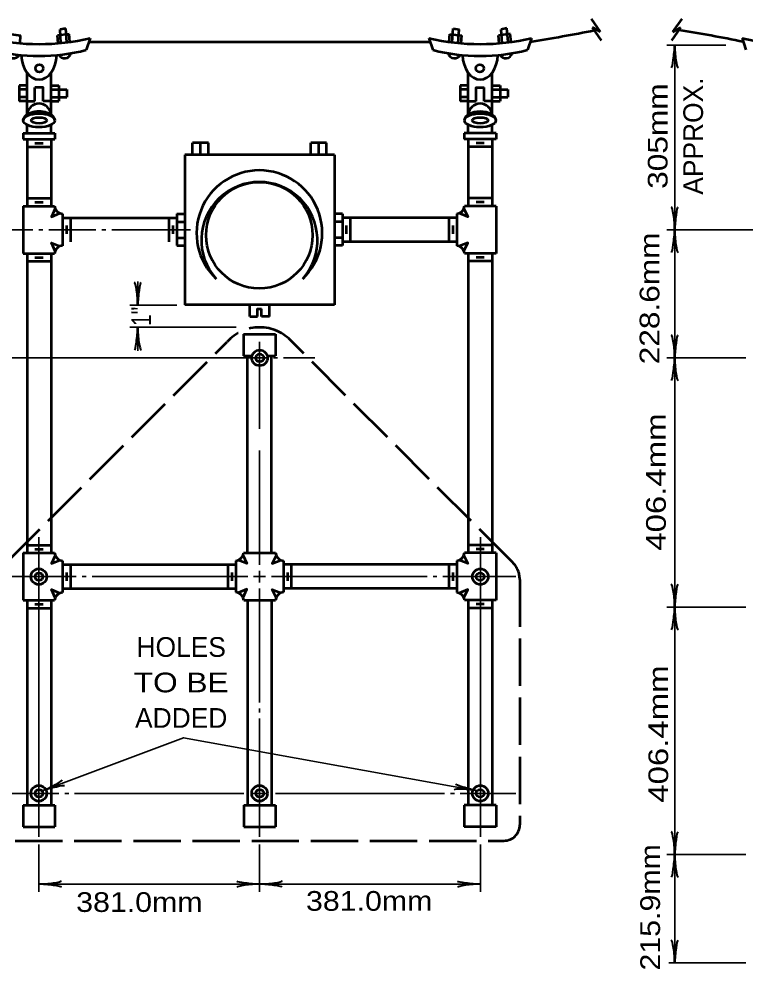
# Model space of a CAD drawing. Extents: x -35 to 821, y -10 to 534.
# Drawn here: x 78 to 188.7, y 242.7 to 387.3 of the extents above; entities that cross this region are included whole.
import ezdxf
from ezdxf.enums import TextEntityAlignment as Align

# ---------------------------------------------------------------- set-up
doc = ezdxf.new("R2010")
doc.units = 0
doc.header["$LTSCALE"] = 1.2
doc.linetypes.add('LONG_DASHED', pattern=[7.5, 6, -1.5])
doc.layers.add('1', color=7, linetype='Continuous', lineweight=35)

msp = doc.modelspace()

# ---------------------------------------------------------------- linework, layer by layer
at = {"layer": '1', "lineweight": 53}
for p, q in [((166.54, 385.374), (165.163, 387.34)), ((177.582, 385.374), (178.959, 387.34)), ((76.491, 385.075), (78.275, 384.834)), ((78.192, 383.649), (78.275, 384.834)), ((85.696, 385.031), (83.895, 384.831)), ((83.977, 383.649), (83.895, 384.831)), ((85.184, 385.898), (84.281, 385.76)), ((84.427, 383.665), (84.281, 385.76)), ((85.33, 383.803), (85.184, 385.898)), ((85.778, 383.85), (85.696, 385.031)), ((143.534, 383.85), (143.616, 385.031)), ((143.616, 385.031), (145.417, 384.831)), ((143.982, 383.803), (144.128, 385.898)), ((144.128, 385.898), (145.031, 385.76)), ((144.885, 383.665), (145.031, 385.76)), ((145.335, 383.649), (145.417, 384.831)), ((152.821, 385.075), (151.037, 384.834)), ((151.12, 383.649), (151.037, 384.834)), ((152.294, 385.932), (151.424, 385.763)), ((151.57, 383.668), (151.424, 385.763)), ((152.477, 383.84), (152.294, 385.932)), ((152.928, 383.851), (152.821, 385.075)), ((166.723, 384.055), (165.346, 386.021)), ((166.54, 385.374), (165.346, 386.021)), ((177.399, 384.055), (178.776, 386.021)), ((177.582, 385.374), (178.776, 386.021)), ((88.883, 384.427), (88.283, 382.627)), ((88.693, 383.857), (140.619, 383.857)), ((140.429, 384.427), (141.029, 382.627)), ((156.029, 384.427), (155.429, 382.627)), ((188.093, 384.427), (188.693, 382.627)), ((79.256, 372.783), (79.256, 379.155)), ((82.91, 372.783), (82.91, 379.155)), ((146.402, 372.783), (146.402, 379.155)), ((150.056, 372.783), (150.056, 379.155)), ((79.256, 377.227), (78.056, 377.227)), ((78.056, 377.227), (78.056, 374.827)), ((79.256, 376.627), (78.056, 376.627)), ((80.456, 374.827), (80.456, 376.927)), ((82.91, 377.227), (84.11, 377.227)), ((82.91, 376.627), (85.31, 376.627)), ((84.11, 377.227), (84.11, 374.827)), ((85.31, 376.627), (85.31, 375.427)), ((146.402, 377.227), (145.202, 377.227)), ((145.202, 377.227), (145.202, 374.827)), ((146.402, 376.627), (145.202, 376.627)), ((148.856, 374.827), (148.856, 376.927)), ((150.056, 377.227), (151.256, 377.227)), ((150.056, 376.627), (152.456, 376.627)), ((151.256, 377.227), (151.256, 374.827)), ((152.456, 376.627), (152.456, 375.427)), ((79.256, 375.427), (78.056, 375.427)), ((79.256, 374.827), (78.056, 374.827)), ((79.256, 374.827), (80.456, 374.827)), ((82.91, 374.827), (81.71, 374.827)), ((82.91, 375.427), (85.31, 375.427)), ((82.91, 374.827), (84.11, 374.827)), ((146.402, 375.427), (145.202, 375.427)), ((146.402, 374.827), (145.202, 374.827)), ((146.402, 374.827), (147.602, 374.827)), ((150.056, 374.827), (148.856, 374.827)), ((150.056, 375.427), (152.456, 375.427)), ((150.056, 374.827), (151.256, 374.827)), ((79.256, 369.958), (79.256, 371.227)), ((82.91, 369.958), (82.91, 371.227)), ((146.402, 369.958), (146.402, 371.227)), ((150.056, 369.958), (150.056, 371.227)), ((78.656, 369.958), (83.51, 369.958)), ((78.656, 369.958), (78.656, 369.058)), ((78.656, 369.058), (83.51, 369.058)), ((79.256, 369.058), (79.256, 358.858)), ((82.91, 369.058), (82.91, 358.858)), ((83.51, 369.958), (83.51, 369.058)), ((150.656, 369.958), (145.802, 369.958)), ((145.802, 369.958), (145.802, 369.058)), ((150.656, 369.058), (145.802, 369.058)), ((146.402, 369.058), (146.402, 358.858)), ((150.056, 369.058), (150.056, 358.858)), ((150.656, 369.958), (150.656, 369.058)), ((79.256, 367.858), (82.91, 367.858)), ((80.456, 368.458), (81.71, 368.458)), ((104.456, 366.685), (104.456, 368.485)), ((106.856, 368.485), (104.456, 368.485)), ((105.656, 366.685), (105.656, 368.485)), ((106.856, 366.685), (106.856, 368.485)), ((122.456, 366.685), (122.456, 368.485)), ((124.856, 368.485), (122.456, 368.485)), ((123.656, 366.685), (123.656, 368.485)), ((124.856, 366.685), (124.856, 368.485)), ((150.056, 367.858), (146.402, 367.858)), ((148.856, 368.458), (147.602, 368.458)), ((126.056, 366.685), (103.256, 366.685)), ((103.256, 366.685), (103.256, 343.843)), ((126.056, 366.685), (126.056, 343.843)), ((78.656, 358.858), (83.455, 358.858)), ((78.656, 358.858), (78.656, 351.658)), ((79.256, 360.058), (82.91, 360.058)), ((80.456, 359.458), (81.71, 359.458)), ((150.656, 358.858), (145.857, 358.858)), ((150.056, 360.058), (146.402, 360.058)), ((148.856, 359.458), (147.602, 359.458)), ((150.656, 358.858), (150.656, 351.658)), ((84.656, 357.685), (84.656, 352.83)), ((102.056, 357.685), (102.056, 352.843)), ((102.056, 357.685), (103.256, 357.685)), ((127.256, 357.685), (126.056, 357.685)), ((127.256, 357.685), (127.256, 352.843)), ((144.656, 357.685), (144.656, 352.83)), ((84.656, 357.084), (102.056, 357.084)), ((85.256, 355.885), (85.256, 354.63)), ((85.856, 357.084), (85.856, 353.43)), ((100.856, 357.084), (100.856, 353.43)), ((101.456, 355.885), (101.456, 354.63)), ((102.056, 356.485), (103.256, 356.485)), ((127.256, 356.485), (126.056, 356.485)), ((144.656, 357.084), (127.256, 357.084)), ((127.856, 355.885), (127.856, 354.63)), ((128.456, 357.084), (128.456, 353.43)), ((143.456, 357.084), (143.456, 353.43)), ((144.056, 355.885), (144.056, 354.63)), ((102.056, 354.043), (103.256, 354.043)), ((127.256, 354.043), (126.056, 354.043)), ((144.656, 353.43), (127.256, 353.43)), ((78.656, 351.658), (83.45, 351.658)), ((79.256, 351.658), (79.256, 306.058)), ((79.256, 351.658), (82.91, 351.658)), ((82.91, 351.658), (82.91, 306.058)), ((102.056, 352.843), (103.256, 352.843)), ((127.256, 352.843), (126.056, 352.843)), ((150.656, 351.658), (145.862, 351.658)), ((146.402, 351.658), (146.402, 306.058)), ((150.056, 351.658), (146.402, 351.658)), ((150.056, 351.658), (150.056, 306.058)), ((79.256, 350.458), (82.91, 350.458)), ((80.456, 351.058), (81.71, 351.058)), ((150.056, 350.458), (146.402, 350.458)), ((148.856, 351.058), (147.602, 351.058)), ((126.056, 343.843), (103.256, 343.843)), ((113.156, 342.043), (113.156, 343.843)), ((114.956, 342.043), (114.956, 343.243)), ((116.156, 342.043), (116.156, 343.843)), ((113.156, 342.043), (114.356, 342.043)), ((116.156, 342.043), (114.956, 342.043)), ((112.229, 339.377), (117.083, 339.377)), ((112.229, 339.377), (112.229, 336.077)), ((117.083, 339.377), (117.083, 336.077)), ((112.229, 336.077), (113.514, 336.077)), ((112.829, 306.077), (112.829, 336.077)), ((115.821, 336.077), (117.083, 336.077)), ((116.483, 306.077), (116.483, 336.077)), ((79.256, 307.257), (82.91, 307.257)), ((80.456, 306.658), (81.71, 306.658)), ((150.056, 307.257), (146.402, 307.257)), ((148.856, 306.658), (147.602, 306.658)), ((78.656, 306.058), (83.455, 306.058)), ((78.656, 306.058), (78.656, 298.858)), ((112.229, 306.077), (117.083, 306.077)), ((150.656, 306.058), (145.857, 306.058)), ((150.656, 306.058), (150.656, 298.858)), ((84.656, 304.885), (84.656, 300.03)), ((84.656, 304.285), (111.029, 304.285)), ((85.856, 304.285), (85.856, 300.63)), ((109.829, 304.285), (109.829, 300.63)), ((111.029, 304.885), (111.029, 300.077)), ((118.286, 304.884), (118.286, 300.07)), ((144.656, 304.285), (118.286, 304.285)), ((119.486, 304.285), (119.486, 300.63)), ((143.456, 304.285), (143.456, 300.63)), ((144.656, 304.885), (144.656, 300.03)), ((85.256, 303.084), (85.256, 301.83)), ((110.429, 303.084), (110.429, 301.83)), ((118.886, 303.084), (118.886, 301.83)), ((144.056, 303.084), (144.056, 301.83)), ((84.656, 300.63), (111.029, 300.63)), ((144.656, 300.63), (118.286, 300.63)), ((78.656, 298.858), (83.45, 298.858)), ((79.256, 298.858), (79.256, 267.658)), ((80.456, 298.257), (81.71, 298.257)), ((82.91, 298.858), (82.91, 267.658)), ((112.237, 298.877), (117.079, 298.877)), ((112.837, 298.877), (112.837, 267.677)), ((116.479, 298.877), (116.479, 267.677)), ((150.656, 298.858), (145.862, 298.858)), ((146.402, 298.858), (146.402, 267.658)), ((148.856, 298.257), (147.602, 298.257)), ((150.056, 298.858), (150.056, 267.658)), ((79.256, 297.658), (82.91, 297.658)), ((150.056, 297.658), (146.402, 297.658)), ((78.656, 267.658), (83.51, 267.658)), ((78.656, 267.658), (78.656, 264.358)), ((83.51, 267.658), (83.51, 264.358)), ((112.237, 267.677), (117.091, 267.677)), ((112.237, 267.677), (112.237, 264.377)), ((117.091, 267.677), (117.091, 264.377)), ((150.656, 267.658), (145.802, 267.658)), ((145.802, 267.658), (145.802, 264.358)), ((150.656, 267.658), (150.656, 264.358)), ((78.656, 264.358), (83.51, 264.358)), ((112.237, 264.377), (117.091, 264.377)), ((150.656, 264.358), (145.802, 264.358))]:
    msp.add_line(p, q, dxfattribs=at)
at = {"layer": '1'}
for p, q in [((185.609, 383.373), (176.639, 383.373)), ((177.839, 355.257), (177.839, 383.373)), ((80.156, 355.257), (61.829, 355.257)), ((81.056, 355.257), (81.656, 355.257)), ((82.556, 355.257), (89.756, 355.257)), ((90.656, 355.257), (91.256, 355.257)), ((92.156, 355.257), (104.156, 355.257)), ((194.966, 355.257), (176.639, 355.257)), ((96.11, 343.791), (96.11, 347.391)), ((94.91, 343.791), (102.056, 343.791)), ((94.91, 340.407), (111.083, 340.407)), ((96.11, 340.407), (96.11, 336.807)), ((114.656, 338.177), (114.656, 324.977)), ((61.829, 335.777), (115.883, 335.777)), ((116.783, 335.777), (117.383, 335.777)), ((118.283, 335.777), (123.083, 335.777)), ((176.639, 335.777), (188.666, 335.777)), ((114.656, 321.677), (114.656, 304.257)), ((81.055, 308.458), (81.055, 262.858)), ((148.257, 308.458), (148.257, 262.858)), ((75.656, 302.458), (86.756, 302.458)), ((87.656, 302.458), (88.256, 302.458)), ((89.156, 302.458), (112.856, 302.458)), ((113.756, 302.458), (115.556, 302.458)), ((140.156, 302.458), (116.456, 302.458)), ((141.656, 302.458), (141.056, 302.458)), ((153.656, 302.458), (142.556, 302.458)), ((114.656, 300.658), (114.656, 283.277)), ((188.666, 297.831), (176.639, 297.831)), ((114.656, 282.377), (114.656, 281.777)), ((114.656, 280.877), (114.656, 262.858)), ((75.656, 269.458), (84.11, 269.458)), ((85.01, 269.458), (85.61, 269.458)), ((86.51, 269.458), (112.237, 269.458)), ((113.457, 269.458), (115.857, 269.458)), ((142.802, 269.458), (117.079, 269.458)), ((144.302, 269.458), (143.702, 269.458)), ((153.656, 269.458), (145.202, 269.458)), ((81.055, 261.658), (81.055, 254.458)), ((114.656, 261.658), (114.656, 254.458)), ((148.257, 261.658), (148.257, 254.458)), ((176.639, 260.159), (188.666, 260.159)), ((188.666, 243.657), (176.939, 243.657))]:
    msp.add_line(p, q, dxfattribs=at)
at = {"layer": '1', "linetype": 'LONG_DASHED', "lineweight": 53}
for p, q in [((76.11, 304.583), (109.711, 338.184)), ((153.202, 304.583), (119.6, 338.184)), ((154.256, 302.037), (154.256, 264.658)), ((77.456, 262.257), (151.856, 262.257))]:
    msp.add_line(p, q, dxfattribs=at)
at = {"layer": '1', "lineweight": 53}
for points in [[(81.71, 374.827), (81.71, 376.927), (80.456, 376.927)], [(147.602, 374.827), (147.602, 376.927), (148.856, 376.927)], [(83.549, 358.494), (82.967, 357.238), (84.276, 357.775)], [(145.763, 358.494), (146.345, 357.238), (145.036, 357.775)], [(83.544, 352.021), (82.962, 353.276), (84.272, 352.739)], [(145.768, 352.021), (146.35, 353.276), (145.04, 352.739)], [(114.356, 342.043), (114.356, 343.243), (114.956, 343.243)], [(83.549, 305.694), (82.967, 304.438), (84.276, 304.975)], [(112.133, 305.694), (112.715, 304.438), (111.405, 304.975)], [(117.179, 305.694), (116.597, 304.438), (117.907, 304.975)], [(145.763, 305.694), (146.345, 304.438), (145.036, 304.975)], [(83.544, 299.221), (82.962, 300.476), (84.272, 299.939)], [(112.141, 299.267), (112.723, 300.523), (111.413, 299.986)], [(117.174, 299.26), (116.593, 300.516), (117.902, 299.979)], [(145.768, 299.221), (146.35, 300.476), (145.04, 299.939)]]:
    msp.add_lwpolyline(points, dxfattribs=at)
at = {"layer": '1'}
for points in [[(177.839, 355.257), (177.839, 335.777), (177.839, 297.831), (177.839, 260.159), (177.839, 243.657)], [(114.656, 301.558), (114.656, 302.458), (114.656, 303.358)], [(81.554, 269.833), (103.095, 277.941), (147.785, 269.866)], [(81.055, 255.657), (114.656, 255.657), (148.257, 255.657)]]:
    msp.add_lwpolyline(points, dxfattribs=at)
at = {"layer": '1', "lineweight": 53}
for centre, radius in [((81.136, 379.834), 0.6), ((148.175, 379.834), 0.6), ((114.619, 354.421), 8.1), ((114.667, 335.747), 1.2), ((114.685, 335.747), 0.6), ((81.061, 302.45), 1.2), ((81.079, 302.45), 0.6), ((148.251, 302.45), 1.2), ((148.233, 302.45), 0.6), ((81.062, 269.466), 1.2), ((114.657, 269.466), 1.2), ((148.25, 269.466), 1.2), ((81.08, 269.466), 0.6), ((114.675, 269.466), 0.6), ((148.232, 269.466), 0.6)]:
    msp.add_circle(centre, radius, dxfattribs=at)
for centre, radius, start, end in [((105.196, 692.04), 312.316, 279.33196, 281.15709), ((151.206, 206.674), 181.022, 78.18089, 81.33006), ((81.083, 417.777), 34.25, 256.83593, 283.1638), ((148.229, 417.777), 34.25, 256.8362, 283.16407), ((195.893, 417.777), 34.25, 256.83593, 283.1638), ((81.083, 410.977), 29.25, 255.74997, 284.25003), ((77.196, 382.342), 0.986, 192.33045, 332.21364), ((84.972, 382.342), 0.986, 207.78636, 347.66955), ((148.229, 410.977), 29.25, 255.74997, 284.25003), ((144.339, 382.342), 0.986, 192.33045, 332.21364), ((152.115, 382.342), 0.986, 207.78636, 347.66955), ((81.083, 372.624), 1.834, 4.98578, 175.01422), ((148.229, 372.624), 1.834, 4.98578, 175.01422), ((114.631, 354.737), 9.57, 313.60282, 226.39718), ((114.631, 353.683), 8.837, 318.31863, 221.68137), ((84.77, 359.003), 1.324, 186.32364, 248.08344), ((144.541, 359.003), 1.324, 291.91656, 353.67636), ((84.77, 359.003), 1.324, 202.62687, 248.08262), ((84.77, 359.003), 1.324, 248.08344, 265.0377), ((144.541, 359.003), 1.324, 274.9623, 291.91656), ((144.541, 359.003), 1.324, 291.91738, 337.37313), ((84.766, 351.511), 1.324, 111.91656, 173.65459), ((84.766, 351.511), 1.324, 111.91738, 157.37313), ((84.766, 351.511), 1.324, 94.77118, 111.91656), ((144.546, 351.511), 1.324, 68.08344, 85.22882), ((144.546, 351.511), 1.324, 6.34541, 68.08344), ((144.546, 351.511), 1.324, 22.62687, 68.08262), ((84.77, 306.203), 1.324, 186.32364, 248.08344), ((84.77, 306.203), 1.324, 202.62687, 248.08262), ((110.911, 306.203), 1.324, 291.91656, 354.5292), ((110.911, 306.203), 1.324, 291.91738, 337.37313), ((118.401, 306.203), 1.324, 185.4708, 248.08344), ((118.401, 306.203), 1.324, 202.62687, 248.08262), ((144.541, 306.203), 1.324, 291.91656, 353.67636), ((144.541, 306.203), 1.324, 291.91738, 337.37313), ((84.77, 306.203), 1.324, 248.08344, 265.0377), ((110.911, 306.203), 1.324, 275.11437, 291.91656), ((118.401, 306.203), 1.324, 248.08344, 265.0377), ((144.541, 306.203), 1.324, 274.9623, 291.91656), ((84.766, 298.711), 1.324, 111.91656, 173.65459), ((84.766, 298.711), 1.324, 111.91738, 157.37313), ((84.766, 298.711), 1.324, 94.77118, 111.91656), ((110.919, 298.758), 1.324, 68.08344, 85.22882), ((110.919, 298.758), 1.324, 5.16652, 68.08344), ((110.919, 298.758), 1.324, 22.62687, 68.08262), ((118.396, 298.751), 1.324, 111.91656, 174.5292), ((118.396, 298.751), 1.324, 111.91738, 157.37313), ((118.396, 298.751), 1.324, 94.77118, 111.91656), ((144.546, 298.711), 1.324, 68.08344, 85.22882), ((144.546, 298.711), 1.324, 6.34541, 68.08344), ((144.546, 298.711), 1.324, 22.62687, 68.08262)]:
    msp.add_arc(centre, radius, start, end, dxfattribs=at)
at = {"layer": '1', "linetype": 'LONG_DASHED', "lineweight": 53}
for centre, radius, start, end in [((114.656, 333.78), 6.621, 41.68937, 138.31063), ((150.656, 302.037), 3.6, 0, 45), ((151.856, 264.658), 2.4, 270, 0)]:
    msp.add_arc(centre, radius, start, end, dxfattribs=at)
at = {"layer": '1', "lineweight": 40}
for centre, major_axis, ratio, start_param, end_param in [((177.585, 382.028), (0.211, 2.108), 0.07063, 3.1407148, 5.41811), ((177.585, 382.028), (0.211, 2.108), 0.07063, 3.1407148, 5.41811), ((178.171, 382.064), (-0.187, 2.143), 0.122415, 0.8963533, 3.1415927), ((178.171, 382.064), (-0.187, 2.143), 0.122415, 0.8963533, 3.1415927), ((177.507, 356.567), (0.187, -2.143), 0.122415, 0.8963533, 3.1415927), ((177.507, 356.567), (0.187, -2.143), 0.122415, 0.8963533, 3.1415927), ((178.093, 356.602), (-0.211, -2.108), 0.07063, 3.1407148, 5.41811), ((178.093, 356.602), (-0.211, -2.108), 0.07063, 3.1407148, 5.41811), ((177.585, 353.913), (0.211, 2.108), 0.07063, 3.1407148, 5.41811), ((177.585, 353.913), (0.211, 2.108), 0.07063, 3.1407148, 5.41811), ((178.171, 353.948), (-0.187, 2.143), 0.122415, 0.8963533, 3.1415927), ((178.171, 353.948), (-0.187, 2.143), 0.122415, 0.8963533, 3.1415927), ((95.778, 345.1), (0.187, -2.143), 0.122415, 0.8963533, 3.1415927), ((95.778, 345.1), (0.187, -2.143), 0.122415, 0.8963533, 3.1415927), ((96.364, 345.135), (-0.211, -2.108), 0.07063, 3.1407148, 5.41811), ((96.364, 345.135), (-0.211, -2.108), 0.07063, 3.1407148, 5.41811), ((95.856, 339.062), (0.211, 2.108), 0.07063, 3.1407148, 5.41811), ((96.442, 339.097), (-0.187, 2.143), 0.122415, 0.8963533, 3.1415927), ((177.507, 337.086), (0.187, -2.143), 0.122415, 0.8963533, 3.1415927), ((177.507, 337.086), (0.187, -2.143), 0.122415, 0.8963533, 3.1415927), ((178.093, 337.121), (-0.211, -2.108), 0.07063, 3.1407148, 5.41811), ((178.093, 337.121), (-0.211, -2.108), 0.07063, 3.1407148, 5.41811), ((177.585, 334.432), (0.211, 2.108), 0.07063, 3.1407148, 5.41811), ((177.585, 334.432), (0.211, 2.108), 0.07063, 3.1407148, 5.41811), ((178.171, 334.467), (-0.187, 2.143), 0.122415, 0.8963533, 3.1415927), ((178.171, 334.467), (-0.187, 2.143), 0.122415, 0.8963533, 3.1415927), ((177.507, 299.141), (0.187, -2.143), 0.122415, 0.8963533, 3.1415927), ((177.507, 299.141), (0.187, -2.143), 0.122415, 0.8963533, 3.1415927), ((178.093, 299.176), (-0.211, -2.108), 0.07063, 3.1407148, 5.41811), ((178.093, 299.176), (-0.211, -2.108), 0.07063, 3.1407148, 5.41811), ((177.585, 296.486), (0.211, 2.108), 0.07063, 3.1407148, 5.41811), ((177.585, 296.486), (0.211, 2.108), 0.07063, 3.1407148, 5.41811), ((178.171, 296.522), (-0.187, 2.143), 0.122415, 0.8963533, 3.1415927), ((178.171, 296.522), (-0.187, 2.143), 0.122415, 0.8963533, 3.1415927), ((82.663, 270.605), (-1.939, -0.93), 0.122415, 0.8963533, 3.1415927), ((82.663, 270.605), (-1.939, -0.93), 0.122415, 0.8963533, 3.1415927), ((82.902, 270.069), (2.047, 0.545), 0.07063, 6.2823074, 8.5597026), ((82.902, 270.069), (2.047, 0.545), 0.07063, 6.2823074, 8.5597026), ((146.507, 270.355), (2.037, -0.582), 0.07063, 3.1407148, 5.41811), ((146.507, 270.355), (2.037, -0.582), 0.07063, 3.1407148, 5.41811), ((146.437, 269.772), (2.142, -0.197), 0.122415, 0.8963533, 3.1415927), ((146.437, 269.772), (2.142, -0.197), 0.122415, 0.8963533, 3.1415927), ((177.507, 261.469), (0.187, -2.143), 0.122415, 0.8963533, 3.1415927), ((178.093, 261.504), (-0.211, -2.108), 0.07063, 3.1407148, 5.41811), ((177.585, 258.815), (0.211, 2.108), 0.07063, 3.1407148, 5.41811), ((177.585, 258.815), (0.211, 2.108), 0.07063, 3.1407148, 5.41811), ((178.171, 258.85), (-0.187, 2.143), 0.122415, 0.8963533, 3.1415927), ((178.171, 258.85), (-0.187, 2.143), 0.122415, 0.8963533, 3.1415927), ((82.365, 255.989), (-2.143, -0.187), 0.122415, 0.8963533, 3.1415927), ((82.365, 255.989), (-2.143, -0.187), 0.122415, 0.8963533, 3.1415927), ((113.311, 255.911), (2.108, -0.211), 0.07063, 3.1407148, 5.41811), ((113.311, 255.911), (2.108, -0.211), 0.07063, 3.1407148, 5.41811), ((115.965, 255.989), (-2.143, -0.187), 0.122415, 0.8963533, 3.1415927), ((115.965, 255.989), (-2.143, -0.187), 0.122415, 0.8963533, 3.1415927), ((146.912, 255.911), (2.108, -0.211), 0.07063, 3.1407148, 5.41811), ((146.912, 255.911), (2.108, -0.211), 0.07063, 3.1407148, 5.41811), ((82.4, 255.404), (-2.108, 0.211), 0.07063, 3.1407148, 5.41811), ((82.4, 255.404), (-2.108, 0.211), 0.07063, 3.1407148, 5.41811), ((113.346, 255.326), (2.143, 0.187), 0.122415, 0.8963533, 3.1415927), ((113.346, 255.326), (2.143, 0.187), 0.122415, 0.8963533, 3.1415927), ((116.001, 255.404), (-2.108, 0.211), 0.07063, 3.1407148, 5.41811), ((116.001, 255.404), (-2.108, 0.211), 0.07063, 3.1407148, 5.41811), ((146.947, 255.326), (2.143, 0.187), 0.122415, 0.8963533, 3.1415927), ((146.947, 255.326), (2.143, 0.187), 0.122415, 0.8963533, 3.1415927), ((177.507, 244.967), (0.187, -2.143), 0.122415, 0.8963533, 3.1415927), ((177.507, 244.967), (0.187, -2.143), 0.122415, 0.8963533, 3.1415927), ((178.093, 245.002), (-0.211, -2.108), 0.07063, 3.1407148, 5.41811), ((178.093, 245.002), (-0.211, -2.108), 0.07063, 3.1407148, 5.41811)]:
    msp.add_ellipse(centre, major_axis=major_axis, ratio=ratio, start_param=start_param, end_param=end_param, dxfattribs=at)
at = {"layer": '1', "lineweight": 53}
for centre, major_axis, ratio, start_param, end_param in [((81.083, 382.027), (0, 3.9), 0.692308, 1.615522, 4.6676498), ((148.229, 382.027), (0, 3.9), 0.692308, 1.6155355, 4.6676633), ((81.083, 371.908), (2.4, 0), 0.5625, 6.2831853, 9.424778), ((148.229, 371.908), (-2.4, 0), 0.5625, 3.1415927, 6.2831853)]:
    msp.add_ellipse(centre, major_axis=major_axis, ratio=ratio, start_param=start_param, end_param=end_param, dxfattribs=at)
for centre, major_axis, ratio in [((81.083, 371.908), (2.4, 0), 0.4375), ((81.083, 371.908), (1.2, 0), 0.375), ((148.229, 371.908), (-2.4, 0), 0.4375), ((148.229, 371.908), (-1.2, 0), 0.375)]:
    msp.add_ellipse(centre, major_axis=major_axis, ratio=ratio, dxfattribs=at)

# ---------------------------------------------------------------- texts
at = {"layer": '1'}
msp.add_text('APPROX.', height=3, rotation=90, dxfattribs=at).set_placement((182.153, 369.514), align=Align.CENTER)
at = {"layer": '1', "width": 1.2}
msp.add_text('305mm', height=3, rotation=90, dxfattribs=at).set_placement((176.753, 369.514), align=Align.CENTER)
at = {"layer": '1'}
for s, width, p in [('228.6mm', 1.2, (175.508, 334.775)), ('1"', 0.8, (98.142, 340.607)), ('406.4mm', 1.25, (176.489, 306.398)), ('406.4mm', 1.25, (176.845, 268.037)), ('215.9mm', 1.15, (175.604, 242.496))]:
    msp.add_text(s, height=3, rotation=90, dxfattribs=dict(at, width=width)).set_placement(p)
for s, p in [('HOLES', (102.726, 290.245)), ('ADDED', (102.726, 279.445))]:
    msp.add_text(s, height=3, dxfattribs=at).set_placement(p, align=Align.CENTER)
at = {"layer": '1', "width": 1.2}
msp.add_text('TO BE', height=3, dxfattribs=at).set_placement((102.726, 284.845), align=Align.CENTER)
at = {"layer": '1', "width": 1.15}
for p in [(121.723, 251.592), (86.745, 251.415)]:
    msp.add_text('381.0mm', height=3, dxfattribs=at).set_placement(p)

doc.saveas('drawing.dxf')
